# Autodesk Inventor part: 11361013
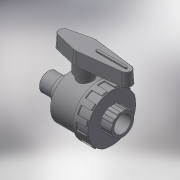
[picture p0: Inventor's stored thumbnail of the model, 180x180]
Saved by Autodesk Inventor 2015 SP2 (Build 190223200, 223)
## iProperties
Created: 2017-11
Part Number: 11361013
Material: Generic
Description: PLASSON ONE NUT VALVE MALE-FEMALE ADAPTOR 1.1/4" PVC
Document SubType Name: Modeling
Designer: KIM
Density: 1 g/cm^3
Appearance: Default
Author: KIM
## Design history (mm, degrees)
derived "113610.ipt"
feature "Solid1::113610.ipt"
tag "TaggingFeature1"
body "Solid1"
other parameters: "d0" = 112, "d4" = 31.1616, "d8" = 72, "d13" = 1.16856, "d25" = 0.77904, "d26" = 1.16856, "d29" = 16.5, "d30" = 0, "d35" = 1.16856, "d45" = 360 deg, "d47" = 0.77904, "d50" = 44, "d51" = 24, "d53" = 0, "d58" = 0, "d59" = 1.16856, "d63" = 32, "d64" = 74, "d66" = 96, "d68" = 16, "d69" = 28.8, "d70" = 18.5, "d71" = 3 deg, "d73" = 1.6, "d74" = 38.4, "d75" = 2.22, "d76" = 0, "d77" = 0.77904, "d78" = 38.952, "d79" = 22, "d81" = 23.1, "d82" = 76.8, "d83" = 17.6, "d84" = 54.5328, "d85" = 29.337, "d87" = 120 deg, "d90" = 360 deg, "d92" = 12, "d95" = 6, "d96" = 41.91, "d97" = 26.4, "d98" = 22, "d99" = 15 deg, "d100" = 50.292, "d101" = 7.7904, "d102" = 3.8952, "G_" = 38.952, "l_" = 22, "H_" = 112, "F_" = 74, "J_" = 96, "R_" = 41.91, "d67" = 32, "d72" = 8
